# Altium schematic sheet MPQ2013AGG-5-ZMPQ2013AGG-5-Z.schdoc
size 127 x 101 mm
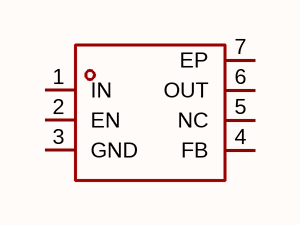
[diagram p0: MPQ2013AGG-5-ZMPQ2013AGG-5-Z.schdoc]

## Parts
U?  mpq2013agg-5-z  [QFN-6_L2.0-W2.0-P0.65-TL-EP]  (value not drawn)

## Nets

Not connected (* = marked no-connect by the designer): U? 1(IN) 2(EN) 3(GND) 4(FB) 5(NC) 6(OUT) 7(EP)

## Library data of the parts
U? = mpq2013agg-5-z: 输出类型:固定;工作电压:40V;输出电压:5V;输出电流:150mA;电源纹波抑制比(PSRR):58dB@(100Hz);输出极性:正极;; Manufacturer: MPS(芯源); AddInBom: yes; ModelId: fb954096014f4050b0970d73f1ef6cc4; ModelName: QFN-6_L2.0-W2.0-H0.8-P0.65; ModelTransform: 78.74,77.961,0,0,0,0,0.0005,0,0; Output Type: 固定; Voltage - Supply: 40V; Output Voltage: 5V; Output Current: 150mA; Output Configuration: 正极; Number of Outputs: 1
